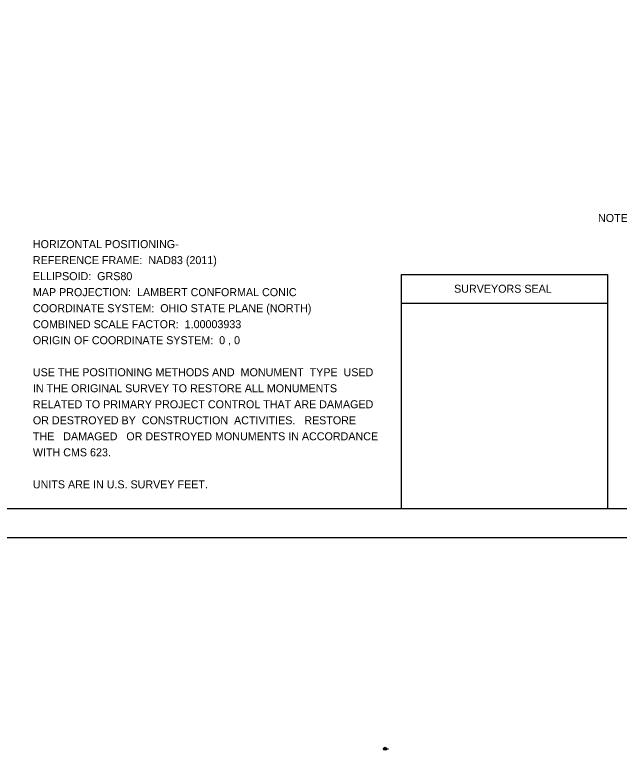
# Model space of a CAD drawing. Extents: x -6.7 to 34, y -3.7 to 22.
# Drawn here: x 10.53 to 21.1, y -3.72 to 9.14 of the extents above; entities that cross this region are included whole.
import ezdxf

# ---------------------------------------------------------------- set-up
doc = ezdxf.new("R2010")
doc.units = 0
for name, color, linetype in [('Default', 7, 'Continuous'), ('SH_Border', 7, 'Continuous'), ('SH_Data', 7, 'Continuous'), ('SH_Named_Boundary', 7, 'Continuous'), ('SH_Text', 7, 'Continuous')]:
    doc.layers.add(name, color=color, linetype=linetype)

msp = doc.modelspace()

# ---------------------------------------------------------------- linework, layer by layer
at = {"layer": 'Default'}
for p, q in [((16.974, -3.693), (17.026, -3.693)), ((17, -3.693), (17.065, -3.693))]:
    msp.add_line(p, q, dxfattribs=at)
msp.add_circle((17, -3.693), 0.026, dxfattribs=at)
at = {"layer": 'SH_Border'}
msp.add_lwpolyline([(1.5, 21.5), (33.5, 21.5), (33.5, 0.5), (1.5, 0.5)], close=True, dxfattribs=at)
at = {"layer": 'SH_Data'}
msp.add_lwpolyline([(0, 0), (34, 0), (34, 22), (0, 22)], close=True, dxfattribs=at)
at = {"layer": 'SH_Named_Boundary'}
msp.add_line((17.288, 4.1), (20.888, 4.1), dxfattribs=at)
msp.add_lwpolyline([(17.288, 4.6), (20.888, 4.6), (20.888, 0.5), (17.288, 0.5)], close=True, dxfattribs=at)

# ---------------------------------------------------------------- texts
at = {"layer": 'Default'}
for s, p in [('156', (16.996, -3.703)), ('2', (16.999, -3.687)), ('108471_RC007', (17.032, -3.687)), ('1:1', (17.032, -3.703))]:
    msp.add_text(s, height=0.00328, dxfattribs=at).set_placement(p)
at = {"layer": 'SH_Named_Boundary'}
msp.add_text('SURVEYORS SEAL', height=0.14, dxfattribs=at).set_placement((18.209, 4.28))
at = {"layer": 'SH_Text'}
for s, p in [('NOTE: THE EXISTING R/W WIDTH AND LOCATION WERE DETERMINED ', (20.724, 5.517)), ('HORIZONTAL POSITIONING-', (10.848, 5.06)), ('REFERENCE FRAME:  NAD83 (2011)', (10.848, 4.78)), ('ELLIPSOID:  GRS80', (10.848, 4.5)), ('MAP PROJECTION:  LAMBERT CONFORMAL CONIC', (10.848, 4.22)), ('COORDINATE SYSTEM:  OHIO STATE PLANE (NORTH)', (10.848, 3.94)), ('COMBINED SCALE FACTOR:  1.00003933', (10.848, 3.66)), ('ORIGIN OF COORDINATE SYSTEM:  0 , 0', (10.848, 3.38)), ('USE THE POSITIONING METHODS AND  MONUMENT  TYPE  USED  ', (10.848, 2.82)), ('IN THE ORIGINAL SURVEY TO RESTORE ALL MONUMENTS ', (10.848, 2.54)), ('RELATED TO PRIMARY PROJECT CONTROL THAT ARE DAMAGED ', (10.848, 2.26)), ('OR DESTROYED BY  CONSTRUCTION  ACTIVITIES.   RESTORE   ', (10.848, 1.98)), ('THE   DAMAGED   OR DESTROYED MONUMENTS IN ACCORDANCE ', (10.848, 1.7)), ('WITH CMS 623.', (10.848, 1.42)), ('UNITS ARE IN U.S. SURVEY FEET.', (10.848, 0.86))]:
    msp.add_text(s, height=0.14, dxfattribs=at).set_placement(p)

doc.saveas('drawing.dxf')
